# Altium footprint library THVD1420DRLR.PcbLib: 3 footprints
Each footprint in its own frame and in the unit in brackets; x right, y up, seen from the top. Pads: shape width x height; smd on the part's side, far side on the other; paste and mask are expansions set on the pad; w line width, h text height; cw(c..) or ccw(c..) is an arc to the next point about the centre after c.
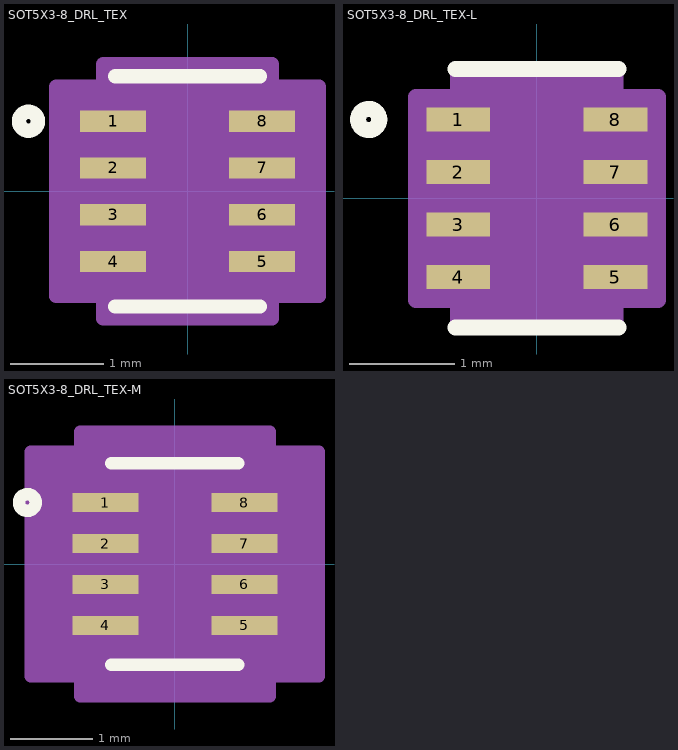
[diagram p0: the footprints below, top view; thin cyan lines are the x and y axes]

## SOT5X3-8_DRL_TEX [mm]
pads (8):
  rect 0.706x0.229 smd paste+0 mask+0: 1(-0.798,0.75) 2(-0.798,0.25) 3(-0.798,-0.25) 4(-0.798,-0.75) 5(0.798,-0.75) 6(0.798,-0.25) 7(0.798,0.25) 8(0.798,0.75)
Top Overlay:
  circle w0.152: c-1.702,0.75 r0.102
  lines w0.152: -0.775,-1.232 0.775,-1.232 ; -0.775,1.232 0.775,1.232
  text ".Designator" at -3.492,-0.635 h1.27
Mechanical 13:
  circle w0.025: c-0.445,0.75 r0.076
  lines w0.025: -0.305,1.105 ccw(c0,1.105) 0.305,1.105 ; -0.648,-1.105 0.648,-1.105 0.648,1.105 -0.648,1.105 -0.648,-1.105
  text ".Designator" at -3.492,-0.635 h1.27
Mechanical 15:
  region: -0.902,-1.119 -1.405,-1.119 -1.405,1.119 -0.902,1.119 -0.902,1.359 0.902,1.359 0.902,1.119 1.405,1.119 1.405,-1.119 0.902,-1.119 0.902,-1.359 -0.902,-1.359
  lines w0.152: -1.405,-1.119 -1.405,1.119 -0.902,1.119 -0.902,1.359 0.902,1.359 0.902,1.119 1.405,1.119 1.405,-1.119 0.902,-1.119 0.902,-1.359 -0.902,-1.359 -0.902,-1.119 -1.405,-1.119
3D body "SOT5X3-8_DRL_TEX.step": height 0.61, standoff 0, extent -0.851,-1.105 0.851,1.105

## SOT5X3-8_DRL_TEX-L [mm]
pads (8):
  rect 0.606x0.229 smd paste+0 mask+0: 1(-0.748,0.75) 2(-0.748,0.25) 3(-0.748,-0.25) 4(-0.748,-0.75) 5(0.748,-0.75) 6(0.748,-0.25) 7(0.748,0.25) 8(0.748,0.75)
Top Overlay:
  circle w0.152: c-1.602,0.75 r0.102
  lines w0.152: -0.775,-1.232 0.775,-1.232 ; -0.775,1.232 0.775,1.232
  text ".Designator" at -3.492,-0.635 h1.27
Mechanical 13:
  circle w0.025: c-0.445,0.75 r0.076
  lines w0.025: -0.305,1.105 ccw(c0,1.105) 0.305,1.105 ; -0.648,-1.105 0.648,-1.105 0.648,1.105 -0.648,1.105 -0.648,-1.105
  text ".Designator" at -3.492,-0.635 h1.27
Mechanical 15:
  region: -0.749,-0.966 -1.152,-0.966 -1.152,0.966 -0.749,0.966 -0.749,1.206 0.749,1.206 0.749,0.966 1.152,0.966 1.152,-0.966 0.749,-0.966 0.749,-1.206 -0.749,-1.206
  lines w0.152: -1.152,-0.966 -1.152,0.966 -0.749,0.966 -0.749,1.206 0.749,1.206 0.749,0.966 1.152,0.966 1.152,-0.966 0.749,-0.966 0.749,-1.206 -0.749,-1.206 -0.749,-0.966 -1.152,-0.966
3D body "SOT5X3-8_DRL_TEX.step": height 0.61, standoff 0, extent -0.851,-1.105 0.851,1.105

## SOT5X3-8_DRL_TEX-M [mm]
pads (8):
  rect 0.806x0.229 smd paste+0 mask+0: 1(-0.848,0.75) 2(-0.848,0.25) 3(-0.848,-0.25) 4(-0.848,-0.75) 5(0.848,-0.75) 6(0.848,-0.25) 7(0.848,0.25) 8(0.848,0.75)
Top Overlay:
  circle w0.152: c-1.802,0.75 r0.102
  lines w0.152: -0.775,-1.232 0.775,-1.232 ; -0.775,1.232 0.775,1.232
  text ".Designator" at -3.492,-0.635 h1.27
Mechanical 13:
  circle w0.025: c-0.445,0.75 r0.076
  lines w0.025: -0.305,1.105 ccw(c0,1.105) 0.305,1.105 ; -0.648,-1.105 0.648,-1.105 0.648,1.105 -0.648,1.105 -0.648,-1.105
  text ".Designator" at -3.492,-0.635 h1.27
Mechanical 15:
  region: -1.156,-1.373 -1.759,-1.373 -1.759,1.373 -1.156,1.373 -1.156,1.613 1.156,1.613 1.156,1.373 1.759,1.373 1.759,-1.373 1.156,-1.373 1.156,-1.613 -1.156,-1.613
  lines w0.152: -1.759,-1.373 -1.759,1.373 -1.156,1.373 -1.156,1.613 1.156,1.613 1.156,1.373 1.759,1.373 1.759,-1.373 1.156,-1.373 1.156,-1.613 -1.156,-1.613 -1.156,-1.373 -1.759,-1.373
3D body "SOT5X3-8_DRL_TEX.step": height 0.61, standoff 0, extent -0.851,-1.105 0.851,1.105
